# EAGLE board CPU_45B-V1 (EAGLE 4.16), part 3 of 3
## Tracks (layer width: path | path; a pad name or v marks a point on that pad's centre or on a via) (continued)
VDD5  (via drill 0.2, 0.2 pad 0.55) (continued)
  other vias: 22.38,40.02 23.17,39.23 23.17,40.02 15.82,53.71 15.25,53.15 16.95,54.85 16.38,54.28 14.69,52.58 38.79,81.47 39.51,82.19 9.48,33.12 11.07,33.58 11.8,32.84 10.65,32.72 12.42,35.61 12.03,36.91 10.05,37.65 10.22,38.61 8.97,38.38 71.31,13.61 70.46,13.89 70.18,14.74 74.48,16.78 74.2,17.62 73.35,17.91 56.1,81.21 55.98,80.08 56.38,79.23 57.34,78.27 58.53,77.87 60.51,79.96 60.34,79 59.66,78.21
  pour Top: 26.83,40.49 23.91,37.57 20.59,40.88 23.52,43.8
  pour Top: 14.01,52.7 16.16,50.55 17.23,51.62 19.89,48.96 22.61,51.68 17.8,56.49
  pour Route2 (isolate 0.2): 5.3,32.78 6.32,28.94 10.73,28.94 15.93,34.14 25.83,34.14 25.83,41.71 15.29,41.68 9.77,47.21 42.46,79.79 44.06,79.78 57.11,66.72 60.85,66.73 66.39,61.18 66.39,56.2 71.54,51.06 71.54,49.59 73.74,47.38 73.69,47.32 73.69,21.19 68.09,15.59 73.74,9.93 89.81,26 85.79,30.01 88.28,32.5 77.19,74.14 73.86,74.98 75.27,80.36 60.73,84.26 57.96,85 40.43,89.64 38.96,84.2 35.56,85.22 5.18,54.85 6.09,51.34 0.71,49.92
  pour Top: 38.15,81.47 40.39,79.23 41.75,80.59 39.51,82.83
  pour Bottom (isolate 0.2): 6.09,31.2 8.97,31.94 10.1,31.94 10.84,31.2 13.67,34.03 12.37,38.5 8.52,39.52 8.29,38.5 7.33,37.99 4.45,37.14
  pour Top (isolate 0.2): 6.09,31.2 8.97,31.94 10.1,31.94 10.84,31.2 13.67,34.03 12.37,38.5 12.21,38.58 12.05,38.58 8.6,39.52 8.29,38.5 7.33,37.99 4.45,37.14
  pour Bottom (isolate 0.2): 77.87,14.63 72.5,20 68.09,15.59 73.46,10.21
  pour Top (isolate 0.2): 77.87,14.63 72.5,20 68.09,15.59 73.46,10.21
  pour Top (isolate 0.2): 56.23,85.16 54.27,77.82 60.29,76.2 62.26,83.54
  pour Bottom (isolate 0.2): 56.23,85.16 54.27,77.82 60.29,76.2 62.26,83.54
VDD5USB  (via drill 0.2, 0.2 pad 0.55)
  Top 0.12: U300.E2 59.35,43.63 60.71,43.63 v61.75,42.59
  Top 0.2: v27.13,63.33 27.11,63.31 v27.7,63.9 | R406.2 76.7,64.57 77.69,63.98 77.68,64 TP407.1
  Top 0.5: C212.1 20.85,64.86 | U200.1 23.04,63.35 22.95,63.44
  Top 0.8: V200.A 20.57,56.43 20.57,57.3 L201.2 20.23,59.18 20.23,59.82 19.1,60.96 19.1,61.63 17.68,63.05 17.68,64.07 19.38,65.76 20,65.76 C212.1 | 22.83,63.56 22.27,64.12 21.59,64.12 20.85,64.86 | 22.83,63.56 22.95,63.44 | 22.83,63.56 23.85,64.58 25.89,64.58 v27.13,63.33 | v27.13,63.33 v26.57,62.77 | v27.13,63.33 v27.7,63.9
  Route2 0.2: 65.49,61.52 65.45,61.47 v65.43,61.47
  Route2 1: v26.57,62.77 42.91,79.11 44.5,79.11 50.76,72.85 50.78,72.83 52.71,72.83 54.39,71.15 54.39,70.13 58.07,66.44 60.56,66.44 65.49,61.52
  Route3 0.12: v61.75,42.59 62.23,42.11 67.03,42.11 v67.19,42.27
  Route14 0.12: v65.43,61.47 68.23,58.67 68.23,51.39 67.59,50.75 67.59,50.11 67.83,49.87 67.83,46.51 67.19,45.87 v67.19,42.27
  Bottom 0.8: TP407.1 75.69,62.03 v64.87,62.03 | v65.43,61.47 v64.87,62.03 | v64.87,62.03 v64.31,62.59
VDDC  (via drill 0.2 pad 0.55)
  Top 0.16: U300.M11 51.75,50.27 51.59,50.43 v51.59,51.15 | v50.15,41.63 | v58.79,39.63 58.95,39.79 U300.A2 | v50.15,41.63 U300.B12 | v50.15,41.63 48.07,41.63 47.69,41.25 C306.1
  Top 0.2: v51.59,51.15 48.79,51.15 48.23,51.71 C307.1 48.23,54.03 48.15,54.11 C308.1 | v58.79,39.63 | v58.79,39.63 | C305.1 58.79,38.55 v58.79,39.63
  Bottom 0.8: v50.15,41.63 50.79,40.99 55.35,40.99 | 55.35,40.99 55.59,40.99 56.95,39.63 v58.79,39.63 | v51.59,51.15 54.31,51.15 55.35,50.11 55.35,40.99
VDDP  (via drill 0.2 pad 0.55)
  Top 0.12: v49.67,48.83 | v51.75,40.03 U300.A11
  Top 0.16: U300.A11 v51.75,40.03 51.75,38.43 51.47,38.15 C301.1 | v49.67,48.83 U300.L12 | U300.B1 60.07,41.63 60.95,40.75 60.95,40.43 v61.35,40.03
  Top 0.2: v49.67,48.83 49.27,48.43 47.91,48.43 47.19,49.15 C302.1 45.71,49.55 C325.1 | JP300.2 50.93,57.71 50.95,57.71 52.34,56.32 54.9,56.32 56.42,54.8 L301.2 | L300.2 64.71,48.34 v64.71,49.71 | C323.1 63.23,38.19 61.75,38.19 C300.1 61.75,39.63 v61.35,40.03 | C301.1 51.47,37.27 51.27,37.07 50.23,37.07 48.63,38.67 46.83,38.67 C324.1
  Bottom 0.2: v64.71,49.71 64.23,50.19 v60.55,50.19
  pour Route2: 51.03,59.63 48.31,56.99 48.31,39.55 62.23,39.47 62.23,53.47 54.39,53.47 54.39,56.19
WPORST#  (via drill 0.2)
  Top 0.12: U500.32 43.96,75.79 v43.99,75.79 | C503.1 46.64,77.07 v45.27,77.07 | U501.4 58.31,70.39 58.31,70.19 57.59,69.47 57.39,69.47 U501.6 56.35,70.51 56.31,70.51 56.31,70.43 R503.1 56.22,70.45 56.22,70.69 v55.27,71.63 | v55.27,71.63 | v55.27,71.63
  Route3 0.12: v45.27,77.07 45.75,77.07 47.26,75.56 X501.3 49.04,73.86 51.51,71.39 55.03,71.39 v55.27,71.63
  Bottom 0.12: v45.27,77.07 | v43.99,75.79 v45.27,77.07 | v45.27,77.07
WTCK
  Top 0.12: X501.1 42.79,76.57 42.79,76.03 U500.34
WTMS
  Top 0.12: U500.33 43.81,76.35 44.79,76.35 45.51,75.63 45.51,75.66 X501.2
WUSB_DM
  Top 0.12: U500.3 36.87,70.11 35.99,70.11 35.35,70.75 35.35,72.31 35.11,72.55 35.11,73.07 35.27,73.23 35.25,73.23 R501.1
WUSB_DP
  Top 0.12: U500.4 37.34,69.87 35.87,69.87 35.11,70.63 35.11,72.19 34.87,72.43 34.42,72.43 R502.1
WVDDC  (via drill 0.2 pad 0.55)
  Top 0.2: C505.1 45.67,78.62 45.67,78.75 | 45.67,78.75 45.67,78.83 | v46.31,79.55 45.67,78.91 45.67,78.75
  Top 0.3: U500.6 37.75,68.87 v37.75,68.59 37.37,68.59 C504.1 | U500.31 43.95,75.07 v44.23,75.07 | v41.35,66.19 | C506.1 42.98,66.19 v41.35,66.19
  Route3 0.3: v37.75,68.59 | v37.75,68.59 | v41.35,66.19 39.35,66.19 37.75,67.79 v37.75,68.59 | v37.75,68.59 | v37.75,68.59
  Route14 0.3: v37.75,68.59 | v37.75,68.59 | v37.75,68.59 39.35,70.19 41.35,70.19 42.55,71.39 42.55,73.39 v44.23,75.07 44.71,74.59 45.91,74.59 46.63,75.31 46.63,79.23 v46.31,79.55
(copper drawn outside any net)
  shapes: Bottom area x4412

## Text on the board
Top: Top Layer
Route2: Layer 5 Power
Route3: Layer 3
Route14: Layer 4
Route15: Layer 2 GND
Bottom: www.hitex.com/xmc4000 | www.infineon.com/mcu | JP300 | Made in Germany | GND | + | - | Bottom Layer
bStop: www.hitex.com/xmc4000 | www.infineon.com/mcu | JP300 | GND | + | -
Document: 1/1 | R2 / 26.08.2011 / Ma
Reference: 0.45 x 30° | Anfasung | beideitig (6x) | Samtec | HSEC8-RA | Mechanikplan | 93.57 | MPL | 21.03 | 2.4 | Alle Angaben in [mm] +/-0.1 | 17.82 | 86.60 | 75.00 | 81.03 | 14.70 | 25.08 | 37.50 | 20.99
tBPL: Bestückungsplan | K | BPL
tSilk: 2 | X500 | 1 | 80 | ACT | SJ2 | GND | DEBUG | USB | VDD3.3 | U500 | SJ3 | P1.1 | GND | VDD5 | VDD5USB | + | A | LED2 | JP300 | PowerScale | - | P0.10 | U300 | USB | BUTTON2 | XMC4500 | P5.2 | OTG | + | RESET | X203 | LED1 | P5.10 | BUTTON1 | 80 | U401 | Q302 | COM | Q301 | U430 | Silkscreen | SD-RAM | X402 | U302 | 2 | HMI | SJ1 | SJ4 | ON | 1 | + | SJ5 | OFF | X401 | X400 | R300 | BSL | CAN | P14.1 | UART | 1 | 1 | CPU_45B-V1- | 80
